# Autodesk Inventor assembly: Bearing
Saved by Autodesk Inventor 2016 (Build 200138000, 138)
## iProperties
Created: 2015-08
Part Number: Bearing
Document SubType Name: Assembly
Designer: stank
Mass: 72.9462 g
Surface Area: 85.1408 cm^2
Volume: 9.29251 cm^3
Density: 7.85 g/cm^3
ClientObjectVersion: 1
Author: stank
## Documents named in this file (2)
- E:\Turbokompr\Sklop turbokompresora\Design Accelerator\Bearing2.iam
- C:\Users\stank\Documents\Inventor\Content Center Files\R2016\en-US\BS 292 (V)\BS 292_ Part 1 - N 1005 - 25 x 47 x 12.ipt
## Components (1 placed, 1 different names)
1. BS 292: Part 1 (V) (Metric) N 1005 - 25 x 47 x 12:1
